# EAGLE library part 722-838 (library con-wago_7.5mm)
Serie 722, Federleiste mit abgewinkelten Einlötstiften / Series 722, Female connector with angled solder pins Polzahl / Pole No.: 8 Rastermaß / Pitch: 7.5 mm Bemessungsspannung / Rated Voltage: 630 V Nennstrom / Nominal Current: 12 A Lötstiftlänge: / Solder Pin Length: 5 mm Farbe / Color: lichtgrau / light gray Stand: 01.01.2012. Die jeweils aktuellen Daten zu diesem Artikel finden Sie in unserem Produktkatalog, den Sie unter www.wago.com einsehen können. As of: 01/01/2012. Please find the newest data for this article in our product catalogue, which can be viewed under www.wago.com.
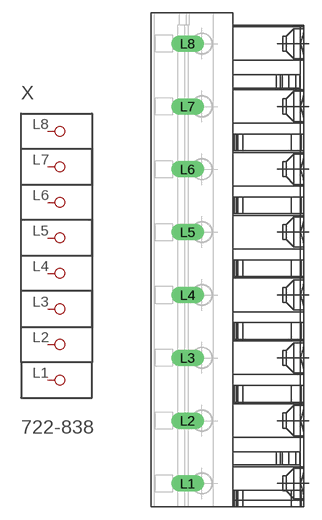
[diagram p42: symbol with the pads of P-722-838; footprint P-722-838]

Designator prefix X

## 722-838  [P-722-838]
L1  P1
L2  P2
L3  P3
L4  P4
L5  P5
L6  P6
L7  P7
L8  P8

## Footprint P-722-838 (pad centres in mm)
drill 1.3 long: L1 -5.042,-26.7; L2 -5.042,-19.2; L3 -5.042,-11.7; L4 -5.042,-4.2; L5 -5.042,3.3; L6 -5.042,10.8; L7 -5.042,18.3; L8 -5.042,25.8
